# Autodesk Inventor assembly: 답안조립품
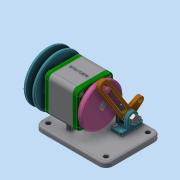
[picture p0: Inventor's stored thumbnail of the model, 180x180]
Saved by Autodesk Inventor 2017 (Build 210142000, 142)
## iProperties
Part Number: 답안조립품
Material: 일반
Document SubType Name: Assembly
Designer: 222
Mass: 1532.4 g
Surface Area: 1486.39 cm^2
Volume: 469.454 cm^3
Density: 3.26422 g/cm^3
Author: 222
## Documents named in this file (19)
- C:\Users\222\Desktop\601106V1060\답안조립품.iam
- C:\Users\222\Desktop\601106V1060\본체.ipt
- C:\Users\222\Desktop\601106V1060\V-벨트풀리.ipt
- C:\Users\222\Desktop\601106V1060\너트 M8.ipt
- C:\Users\222\Desktop\601106V1060\너트 M10x1.ipt
- C:\Users\222\Desktop\601106V1060\돌림판.ipt
- C:\Users\222\Desktop\601106V1060\멈춤나사 M3x5.ipt
- C:\Users\222\Desktop\601106V1060\베어링 6004.ipt
- C:\Users\222\Desktop\601106V1060\볼트 M4.ipt
- C:\Users\222\Desktop\601106V1060\오일 실 17 30 5.ipt
- C:\Users\222\Desktop\601106V1060\와셔 8x15.5.ipt
- C:\Users\222\Desktop\601106V1060\축.ipt
- C:\Users\222\Desktop\601106V1060\커버.ipt
- C:\Users\222\Desktop\601106V1060\크랭크.ipt
- C:\Users\222\Desktop\601106V1060\키 4 x 4 x 8.ipt
- C:\Users\222\Desktop\601106V1060\키 5 x 5 x 12.ipt
- C:\Users\222\Desktop\601106V1060\핀 3 x 8.ipt
- C:\Users\222\Desktop\601106V1060\힌지 축.ipt
- C:\Users\222\Desktop\601106V1060\힌지.ipt
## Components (3 placed, 2 different names)
1. V-벨트풀리:1
2. 핀 3 x 8:1 — 플러쉬:1
3. 핀 3 x 8:2 — 플러쉬:2
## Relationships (2: Flush 2)
- 플러쉬:1 [Flush]: 핀 3 x 8:1
- 플러쉬:2 [Flush]: 핀 3 x 8:2
